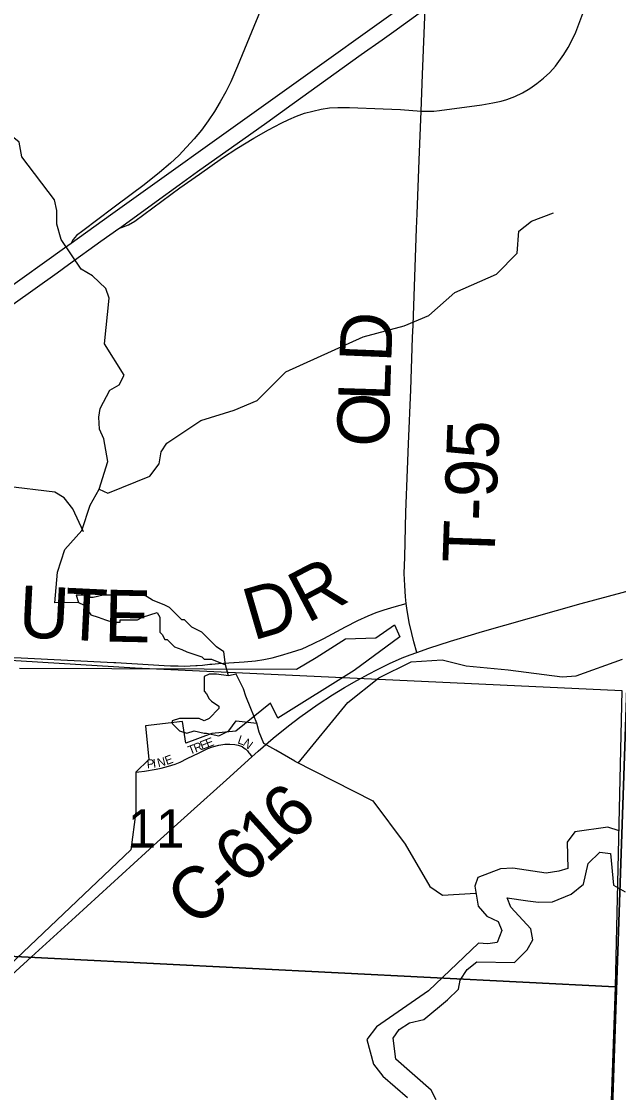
# Model space of a CAD drawing. Extents: x 0 to 34, y 0 to 22.
# Drawn here: x 5.481 to 6.135, y 18.295 to 19.468 of the extents above; entities that cross this region are included whole.
import ezdxf

# ---------------------------------------------------------------- set-up
doc = ezdxf.new("R2010")
doc.units = 0
for name, color, linetype in [('GM_X_Corporation', 7, 'Continuous'), ('GM_X_County_Road', 7, 'Continuous'), ('GM_X_County_Road_Text', 7, 'Continuous'), ('GM_X_Interchange_Ramps', 7, 'Continuous'), ('GM_X_Minor_Lake', 7, 'Continuous'), ('GM_X_Minor_River', 7, 'Continuous'), ('GM_X_Section', 7, 'Continuous'), ('GM_X_Section_Text', 7, 'Continuous'), ('GM_X_State_Route', 7, 'Continuous'), ('GM_X_Township', 7, 'Continuous'), ('GM_X_Township_Road', 7, 'Continuous'), ('GM_X_Township_Road_Text', 7, 'Continuous'), ('GM_X_Township_Subdivision', 7, 'Continuous'), ('GM_X_Township_Subdivision_Text', 7, 'Continuous')]:
    doc.layers.add(name, color=color, linetype=linetype)

msp = doc.modelspace()

# ---------------------------------------------------------------- linework, layer by layer
at = {"layer": 'GM_X_Corporation'}
msp.add_lwpolyline([(5.4787, 18.7598), (5.7821, 18.7586), (5.8035, 18.7717), (5.8356, 18.7919), (5.869, 18.7931), (5.8892, 18.8074), (5.8951, 18.7943), (5.8452, 18.7574), (5.7615, 18.705), (5.7535, 18.7217), (5.7155, 18.6907), (5.6893, 18.6884), (5.6607, 18.6777), (5.6572, 18.7015), (5.6167, 18.6967), (5.6203, 18.6598), (5.6061, 18.6461), (5.606, 18.6027), (5.6005, 18.5608), (5.3716, 18.3439)], dxfattribs=at)
at = {"layer": 'GM_X_County_Road'}
for points in [[(5.9832, 18.7991), (6.0938, 18.8307), (6.1387, 18.8427), (6.1467, 18.8449)], [(5.7139, 18.766), (5.7246, 18.7667), (5.737, 18.7679), (5.7463, 18.7693), (5.7555, 18.7712), (5.7645, 18.7736), (5.7764, 18.7773), (5.7883, 18.7811), (5.8, 18.7863), (5.812, 18.7922), (5.8356, 18.805), (5.8493, 18.8122), (5.8606, 18.8173), (5.8692, 18.8207), (5.878, 18.8238), (5.889, 18.827), (5.8957, 18.8287), (5.9023, 18.8305)], [(5.9137, 18.7771), (5.927, 18.7819), (5.9506, 18.7895), (5.9774, 18.7975), (5.9832, 18.7991)], [(5.3246, 18.7788), (5.328, 18.7787), (5.3455, 18.7777), (5.3805, 18.776), (5.4397, 18.773), (5.4805, 18.771), (5.5819, 18.766), (5.5842, 18.7659), (5.6253, 18.7634), (5.637, 18.7629), (5.6439, 18.7625), (5.6526, 18.7624), (5.6595, 18.7622), (5.6719, 18.7626), (5.6733, 18.7627), (5.6792, 18.7633), (5.6872, 18.7642), (5.6892, 18.7644), (5.6965, 18.765), (5.7135, 18.766), (5.7139, 18.766)], [(5.8617, 18.7537), (5.8699, 18.7581), (5.8838, 18.7649), (5.8979, 18.7712), (5.9066, 18.7746), (5.9137, 18.7771)], [(5.7331, 18.6628), (5.7399, 18.669), (5.7563, 18.6832), (5.7732, 18.6968), (5.7856, 18.7062), (5.8058, 18.7205), (5.8214, 18.7307), (5.8345, 18.7388), (5.848, 18.7465), (5.8617, 18.7537)], [(5.3706, 18.3337), (5.3771, 18.3393), (5.4295, 18.3876), (5.4574, 18.4124), (5.4918, 18.4437), (5.5399, 18.4876), (5.6294, 18.5692), (5.6663, 18.6024), (5.7055, 18.6377), (5.7331, 18.6628)]]:
    msp.add_lwpolyline(points, dxfattribs=at)
at = {"layer": 'GM_X_Interchange_Ramps'}
for points in [[(5.7574, 19.5166), (5.7176, 19.4189), (5.7101, 19.4018), (5.7046, 19.3907), (5.6986, 19.3798), (5.6922, 19.3692), (5.6853, 19.3589), (5.6779, 19.3489), (5.67, 19.3393), (5.6617, 19.3301), (5.653, 19.3212), (5.6439, 19.3128), (5.6321, 19.3026), (5.6151, 19.2891), (5.5854, 19.2667), (5.5808, 19.2633), (5.548, 19.2387), (5.5411, 19.2334), (5.5376, 19.2291), (5.5351, 19.2251)], [(5.9184, 19.3696), (5.9326, 19.3696), (5.9387, 19.3702), (5.985, 19.3765), (5.9972, 19.3786), (6.0063, 19.3807), (6.0123, 19.3825), (6.0211, 19.3858), (6.0295, 19.3898), (6.0376, 19.3945), (6.0453, 19.3998), (6.0525, 19.4057), (6.0593, 19.4121), (6.0656, 19.419), (6.0713, 19.4264), (6.0749, 19.4315), (6.0797, 19.4395), (6.0839, 19.4478), (6.0878, 19.4563), (6.0956, 19.4767)], [(5.5873, 19.2411), (5.598, 19.2452), (5.605, 19.2493), (5.6543, 19.2857), (5.6758, 19.3007), (5.7011, 19.3186), (5.7167, 19.3288), (5.7353, 19.3401), (5.7514, 19.3493), (5.7652, 19.3565), (5.7736, 19.3605), (5.7822, 19.3642), (5.7909, 19.3673), (5.7999, 19.3698), (5.809, 19.3718), (5.8182, 19.3731), (5.8274, 19.3737), (5.8399, 19.3737), (5.877, 19.3721), (5.896, 19.3715), (5.9184, 19.3696)]]:
    msp.add_lwpolyline(points, dxfattribs=at)
at = {"layer": 'GM_X_Minor_Lake'}
for points in [[(5.7044, 18.7635), (5.7025, 18.7777), (5.6944, 18.7831), (5.6863, 18.7912), (5.6782, 18.7993), (5.6674, 18.8047), (5.6593, 18.8128), (5.6566, 18.8128), (5.6458, 18.8235), (5.6431, 18.8263), (5.6377, 18.8289), (5.6242, 18.8343), (5.6107, 18.8425), (5.6053, 18.8425), (5.5972, 18.8397), (5.5837, 18.8397), (5.5702, 18.8397), (5.5594, 18.8371), (5.554, 18.8371), (5.5487, 18.8397), (5.5406, 18.8397), (5.5433, 18.8317)], [(5.5433, 18.8317), (5.5487, 18.829), (5.5514, 18.8263), (5.5568, 18.8182), (5.5648, 18.8155), (5.5729, 18.8128), (5.581, 18.8101), (5.5891, 18.8101), (5.5891, 18.8128), (5.5918, 18.8128), (5.5999, 18.8128), (5.608, 18.8128), (5.6134, 18.8155), (5.6215, 18.8182), (5.6296, 18.8209), (5.6323, 18.8155), (5.6323, 18.8128), (5.6323, 18.8101), (5.6323, 18.8047), (5.6323, 18.7993), (5.635, 18.7966), (5.6377, 18.7912), (5.6404, 18.7912), (5.6485, 18.7831), (5.6566, 18.7804), (5.662, 18.7777), (5.6782, 18.7723), (5.6809, 18.7696), (5.6836, 18.7696), (5.689, 18.7696), (5.7044, 18.7635)], [(5.7074, 18.7514), (5.6944, 18.7534), (5.6917, 18.7534), (5.6863, 18.7534), (5.6809, 18.7507), (5.6809, 18.7372), (5.6809, 18.7345), (5.6836, 18.7318), (5.6863, 18.7264), (5.689, 18.7237), (5.6971, 18.7183), (5.6971, 18.7156), (5.6863, 18.7048), (5.6809, 18.7021), (5.6755, 18.7048), (5.6539, 18.7048), (5.6458, 18.7021), (5.6458, 18.6994), (5.6539, 18.6913), (5.662, 18.6886), (5.6701, 18.6913), (5.6809, 18.6886), (5.6836, 18.6886), (5.6971, 18.6859), (5.7079, 18.6913), (5.7159, 18.7021), (5.7387, 18.6995)], [(5.7387, 18.6995), (5.7321, 18.7156), (5.7267, 18.7291), (5.7241, 18.7372), (5.716, 18.7534), (5.7074, 18.7514)]]:
    msp.add_lwpolyline(points, dxfattribs=at)
at = {"layer": 'GM_X_Minor_River'}
for points in [[(5.547, 18.9106), (5.556, 18.9383), (5.5661, 18.9558), (5.5754, 18.9862), (5.5712, 19.0108), (5.5662, 19.0214), (5.5654, 19.0347), (5.5672, 19.0442), (5.5777, 19.0643), (5.5879, 19.0701), (5.5932, 19.0807), (5.5719, 19.1148), (5.5769, 19.1649), (5.5731, 19.1755), (5.5587, 19.1895), (5.5461, 19.1966), (5.5244, 19.2292), (5.5194, 19.2459), (5.5197, 19.261), (5.517, 19.2724), (5.4813, 19.3197), (5.4782, 19.3356), (5.4633, 19.3477), (5.4596, 19.3417)], [(5.5661, 18.9558), (5.5756, 18.9516), (5.6213, 18.97), (5.6315, 18.9837), (5.6337, 18.9966), (5.6401, 19.0061), (5.6771, 19.0309), (5.7137, 19.0424), (5.7391, 19.0527), (5.7703, 19.0843), (5.855, 19.1226), (5.9, 19.1345), (5.9268, 19.1459), (5.9555, 19.1711), (6.0012, 19.1913), (6.0238, 19.2142), (6.0256, 19.2381), (6.0392, 19.2491), (6.0634, 19.2583)], [(5.5487, 18.9092), (5.5371, 18.9341), (5.5275, 18.9462), (5.5173, 18.9526), (5.4631, 18.9592), (5.4499, 18.9637), (5.4062, 18.9894), (5.391, 18.9992), (5.3668, 19.004), (5.3266, 19.024), (5.2622, 19.0223), (5.2085, 19.0137), (5.1532, 19.0196), (5.122, 19.0461), (5.0736, 19.0417), (5.0638, 19.0429), (5.0539, 19.0493), (5.024, 19.0533), (5.0134, 19.0548), (4.9701, 19.0752), (4.944, 19.0808), (4.8916, 19.1015), (4.8805, 19.1306)], [(5.5433, 18.8317), (5.5174, 18.8312), (5.5203, 18.865), (5.5285, 18.8896), (5.547, 18.9106)], [(5.7074, 18.7514), (5.7044, 18.7635)], [(5.7839, 18.656), (5.8383, 18.7224), (5.8723, 18.7491), (5.9075, 18.7667), (5.9416, 18.7691), (5.9678, 18.7624), (6.014, 18.758), (6.0728, 18.7503), (6.0884, 18.7515), (6.1391, 18.7696)], [(5.7801, 18.6579), (5.7593, 18.67), (5.7464, 18.6772), (5.741, 18.6897), (5.7387, 18.6995)], [(5.7801, 18.6579), (5.8657, 18.6147), (5.9012, 18.5671), (5.9279, 18.5209), (5.942, 18.5115), (5.9786, 18.5135)], [(6.1354, 18.5818), (6.1229, 18.5859), (6.0869, 18.5808), (6.0786, 18.5694), (6.0791, 18.5405), (6.0693, 18.5375), (6.0556, 18.5355), (6.0188, 18.541), (6.0056, 18.5402), (5.9806, 18.5306), (5.9772, 18.5211), (5.9811, 18.4992), (5.9903, 18.4882), (6.0028, 18.4826), (6.007, 18.4727), (6.0018, 18.4594), (5.9915, 18.4582), (5.9813, 18.4586), (5.9266, 18.4067), (5.8695, 18.367), (5.859, 18.3533), (5.8663, 18.3264), (5.8766, 18.3132), (5.9036, 18.2898)], [(5.9351, 18.2873), (5.9294, 18.2979), (5.8909, 18.3318), (5.8878, 18.3546), (5.8946, 18.3641), (5.9059, 18.3714), (5.9214, 18.3752), (5.9475, 18.3966), (5.9595, 18.4084), (5.9614, 18.4183), (5.9689, 18.4301), (5.9795, 18.4384), (6.0208, 18.4375), (6.0348, 18.4516), (6.0408, 18.4626), (6.0388, 18.4744), (6.0167, 18.4982), (6.0129, 18.5084), (6.0353, 18.5051), (6.047, 18.5036), (6.0622, 18.5041), (6.083, 18.5125), (6.0962, 18.5232), (6.1014, 18.546), (6.1143, 18.5585), (6.126, 18.5571), (6.1292, 18.5222), (6.1418, 18.515)]]:
    msp.add_lwpolyline(points, dxfattribs=at)
at = {"layer": 'GM_X_Section'}
for points in [[(5.6053, 18.7602), (6.1384, 18.7353), (6.1311, 18.4108), (5.1195, 18.4619), (5.1294, 18.7895)], [(5.1195, 18.4619), (6.1311, 18.4108), (6.125, 18.2446), (6.1067, 17.7389), (6.0962, 17.4141), (5.0805, 17.4591)]]:
    msp.add_lwpolyline(points, close=True, dxfattribs=at)
at = {"layer": 'GM_X_State_Route'}
for points in [[(5.4596, 19.1711), (5.5278, 19.2199), (5.5351, 19.2251), (5.5782, 19.2562), (5.9237, 19.5033)], [(5.4718, 19.1584), (5.5199, 19.1928), (5.5324, 19.2018), (5.5678, 19.2272), (5.5873, 19.2411), (5.5906, 19.2434), (5.6284, 19.2706), (5.6535, 19.2889), (5.6736, 19.3034), (5.732, 19.3447), (5.7497, 19.3573), (5.7774, 19.3773), (5.853, 19.4318), (5.8758, 19.4479), (5.8885, 19.4569), (5.9162, 19.4769)]]:
    msp.add_lwpolyline(points, dxfattribs=at)
at = {"layer": 'GM_X_Township'}
for points in [[(2.6013, 16.5379), (2.8688, 16.5234), (3.5006, 16.5009), (4.2928, 16.4705), (5.2983, 16.434), (6.0664, 16.4042), (6.0778, 16.7443), (6.0911, 17.2548), (6.11, 17.7459), (6.1473, 18.845), (6.1717, 19.6397), (6.1731, 19.6616), (6.1731, 19.6818), (6.1733, 19.6859), (6.2234, 21.2003)], [(6.2234, 21.2003), (6.1733, 19.6859), (6.1731, 19.6818), (6.1731, 19.6616), (6.1717, 19.6397), (6.1473, 18.845), (6.11, 17.7459), (6.0911, 17.2548), (6.0778, 16.7443), (6.0664, 16.4042), (6.0598, 16.2379), (6.2085, 16.2337), (6.3056, 16.228), (6.5048, 16.2253), (7.5772, 16.1862), (7.7357, 16.1804), (8.4842, 16.1527), (8.5405, 16.1503), (9.1818, 16.131), (9.4013, 16.1226)]]:
    msp.add_lwpolyline(points, dxfattribs=at)
at = {"layer": 'GM_X_Township_Road'}
for points in [[(5.9184, 19.3696), (5.92, 19.4096), (5.9228, 19.4816), (5.9233, 19.4961), (5.9237, 19.5033), (5.9286, 19.6111)], [(5.9097, 19.1355), (5.9135, 19.2412), (5.9143, 19.2573), (5.9162, 19.316), (5.9184, 19.3696)], [(5.9048, 19.0055), (5.9072, 19.0645), (5.9092, 19.1218), (5.9097, 19.1355)], [(5.9023, 18.8305), (5.9015, 18.8378), (5.9005, 18.8503), (5.9001, 18.8635), (5.9005, 18.8813), (5.9018, 18.9308), (5.9036, 18.9772), (5.9048, 19.0055)], [(5.9137, 18.7771), (5.9106, 18.7887), (5.9082, 18.7978), (5.9055, 18.81), (5.9029, 18.8254), (5.9023, 18.8305)]]:
    msp.add_lwpolyline(points, dxfattribs=at)
at = {"layer": 'GM_X_Township_Subdivision'}
msp.add_lwpolyline([(5.606, 18.6461), (5.6094, 18.6464), (5.6155, 18.6472), (5.6284, 18.6492), (5.6339, 18.6504), (5.6418, 18.6524), (5.6492, 18.6549), (5.6545, 18.6571), (5.6622, 18.6608), (5.6755, 18.6673), (5.6851, 18.6718), (5.6902, 18.6738), (5.6969, 18.6757), (5.7036, 18.6765), (5.7089, 18.6765), (5.7144, 18.6761), (5.7183, 18.6755), (5.7224, 18.674), (5.7248, 18.6724), (5.7266, 18.671), (5.7284, 18.6692), (5.7299, 18.6673), (5.7309, 18.6659), (5.7331, 18.6628)], dxfattribs=at)

# ---------------------------------------------------------------- texts
at = {"layer": 'GM_X_County_Road_Text'}
for s, rotation, p in [('R', 27.7097, (5.7937, 18.8084)), ('U', 357.0079, (5.4769, 18.7939)), ('T', 357.2391, (5.5271, 18.7912)), ('E', 358.7716, (5.5712, 18.7891)), ('D', 16.2331, (5.7343, 18.7899)), ('6', 42.2798, (5.7762, 18.5682)), ('1', 42.1123, (5.7501, 18.5446)), ('6', 42.0678, (5.7241, 18.5211)), ('C', 42.0484, (5.6721, 18.4742)), ('-', 42.0496, (5.7068, 18.5055))]:
    msp.add_text(s, height=0.0568, rotation=rotation, dxfattribs=at).set_placement(p)
at = {"layer": 'GM_X_Section_Text'}
msp.add_text('11', height=0.04186, rotation=0, dxfattribs=at).set_placement((5.5972, 18.5634))
at = {"layer": 'GM_X_Township_Road_Text'}
for s, height, rotation, p in [('D', 0.0568, 87.6753, (5.8857, 19.0939)), ('L', 0.0568, 88.2255, (5.8844, 19.0515)), ('O', 0.0568, 88.2329, (5.8828, 19.0015)), ('T-95', 0.05682, 87.9678, (5.9987, 18.8742))]:
    msp.add_text(s, height=height, rotation=rotation, dxfattribs=at).set_placement(p)
at = {"layer": 'GM_X_Township_Subdivision_Text'}
for s, rotation, p in [('E', 21.5376, (5.6785, 18.6702)), ('E', 21.5475, (5.6847, 18.6726)), ('L', 341.8588, (5.7169, 18.6777)), ('N', 323.0645, (5.7225, 18.676)), ('T', 21.5376, (5.6653, 18.665)), ('R', 21.5444, (5.6715, 18.6674)), ('P', 4.9248, (5.6184, 18.6501)), ('I', 5.8514, (5.6252, 18.6507)), ('N', 14.0722, (5.6307, 18.6514)), ('E', 20.1836, (5.6399, 18.6537))]:
    msp.add_text(s, height=0.00947, rotation=rotation, dxfattribs=at).set_placement(p)

doc.saveas('drawing.dxf')
